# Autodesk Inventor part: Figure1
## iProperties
Created: 2001-12
Part Number: Figure1
Document SubType Name: Modeling
Designer: Renu Muthoo
Control State: 0
Master: False
Checked Out: False
Shininess: 77.0
Angle Display Precision: 2
Document Length Units: 11269
Document Angle Units: 11279
Document Time Units: 11290
Document Mass Units: 11283
Document Length Units Precision: 3
Document Angle Units Precision: 2
Density: 0.0
Volumn: 0.0
Area: 0.0
PropertySet Name: Model Information
Author: Renu Muthoo
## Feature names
1. Extrusion1
2. Extrusion3
3. Chamfer3
